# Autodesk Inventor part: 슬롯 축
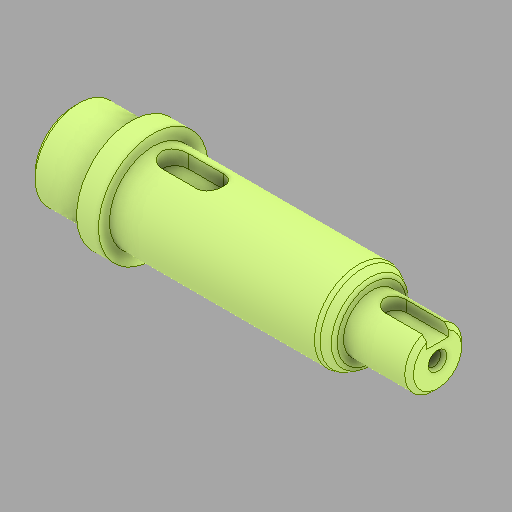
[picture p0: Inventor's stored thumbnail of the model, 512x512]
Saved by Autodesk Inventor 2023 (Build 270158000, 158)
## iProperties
Created: 2025-09
Part Number: 슬롯 축
Material: 강철, 탄소
Document SubType Name: Modeling
Designer: home
Density: 7.85 g/cm^3
Appearance: 기본값
Author: jhkim
Sending System: Autodesk Inventor 2026
Preprocessor: ST-DEVELOPER v20.1
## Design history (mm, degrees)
feature "솔리드1"
node "솔리드2"
